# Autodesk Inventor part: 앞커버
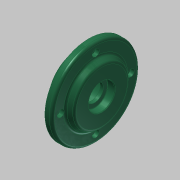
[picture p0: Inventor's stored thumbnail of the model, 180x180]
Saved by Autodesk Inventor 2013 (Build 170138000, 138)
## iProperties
Created: 2015-11
Part Number: 앞커버
Material: 일반
Document SubType Name: Modeling
Designer: mduedu
Density: 1 g/cm^3
Mass: 107.021 g
Surface Area: 234.647 cm^2
Volume: 107.021 cm^3
Author: mduedu
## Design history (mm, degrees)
sketch "스케치1"
  geometry: C1 r 50 at (0, 0); 1 further point
  constraints: 1 centre point, 1 coincident
  dimensions: "d57" = 100 diameter of C1
extrude "돌출1" new body sketch "스케치1" distance "d3" = 8; taper "d4" = 0 deg
sketch "스케치2"
  geometry: C1 r 35 at (0, 0); 1 further point
  constraints: 1 centre point, 1 coincident
  dimensions: "d5" = 70 diameter of C1
extrude "돌출2" join sketch "스케치2" distance "d6" = 7; taper "d7" = -30 deg
sketch "스케치3" dims "d58" = 80
  geometry: 3 further points
  constraints: 2 vertical alignment, 1 coincident, 2 other
hole "구멍1" sketch "스케치3" at (0, 40) diameter "d11" = 4.5; stored, may be unused: countersink angle "d15" = 90 deg, drill point angle "d17" = 118 deg; dims "d12" = 6, "d13" = 8, "d14" = 4.4, "d16" = 8
sketch "스케치4"
  geometry: C1 r 35 at (0, 0); 1 further point
  constraints: 1 centre point, 1 coincident
  dimensions: "d21" = 70 diameter of C1
extrude "돌출3" join sketch "스케치4" distance "d23" = 12; taper "d24" = 0 deg
hole "구멍2" diameter "d27" = 30; stored, may be unused: countersink angle "d31" = 90 deg, drill point angle "d33" = 0 deg; dims "d25" = 10, "d26" = 10, "d28" = 6, "d29" = 40, "d30" = 12, "d32" = 15
fillet "모깎기3" dims "d36" = 3
fillet "모깎기4" dims "d37" = 3
fillet "모깎기5" dims "d38" = 0.3
chamfer "모따기1" distance "d39" = 1; stored, may be unused: second distance "d40" = 2, angle "d41" = 45 deg
hole "구멍3" diameter "d44" = 20; stored, may be unused: countersink angle "d48" = 90 deg, drill point angle "d50" = 118 deg; dims "d45" = 6, "d46" = 30, "d47" = 8.3, "d49" = 8, "d59" = 10, "d60" = 10
fillet "모깎기6" dims "d51" = 0.3
chamfer "모따기2" distance "d52" = 0.8; stored, may be unused: second distance "d53" = 2, angle "d54" = 30 deg
node "솔리드1"
pattern_circular "원형 패턴1" dims angle "d19" = 360 deg
